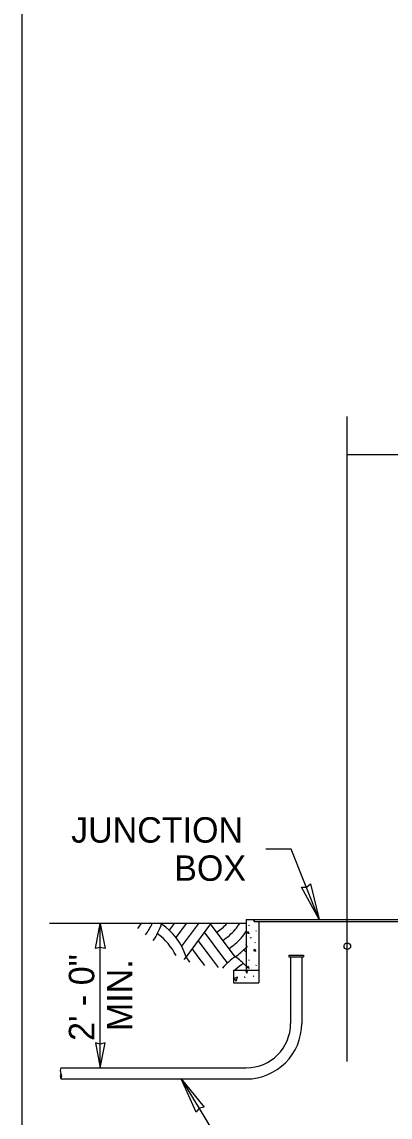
# Model space of a CAD drawing. Extents: x 99862 to 103680, y 99470 to 105076.
# Drawn here: x 99862 to 100094, y 100349 to 101038 of the extents above; entities that cross this region are included whole.
import ezdxf

# ---------------------------------------------------------------- set-up
doc = ezdxf.new("R2010")
doc.units = 0
for name, color, linetype in [('Level 1', 7, 'Continuous'), ('Level 13', 7, 'Continuous'), ('Level 15', 7, 'Continuous'), ('Level 20', 7, 'Continuous'), ('Level 3', 7, 'Continuous')]:
    doc.layers.add(name, color=color, linetype=linetype)

msp = doc.modelspace()

# ---------------------------------------------------------------- linework, layer by layer
at = {"layer": 'Level 1'}
for p, q in [((100003.06, 100472.96), (100003.06, 100441.13)), ((100003.06, 100472.96), (100007.86, 100472.96)), ((100005.03, 100468.93), (100004.85, 100469.35)), ((100007.86, 100472.96), (100007.86, 100471.64)), ((100008.2, 100471.64), (100007.86, 100471.64)), ((100011.02, 100471.64), (100011.02, 100469.62)), ((100011.02, 100469.62), (100011.02, 100441.13)), ((100005.82, 100461.44), (100005.64, 100461.16)), ((100006.14, 100461.55), (100005.95, 100461.27)), ((100009.29, 100465.88), (100009.24, 100465.46)), ((100003.79, 100455.81), (100003.06, 100457.18)), ((100003.06, 100455.86), (100003.74, 100455.81)), ((100008.86, 100458.12), (100008.68, 100458.53)), ((100005.03, 100447.21), (100004.85, 100447.62)), ((99995.1, 100441.13), (99995.1, 100433.17)), ((99995.1, 100441.13), (100011.02, 100441.13)), ((100009.29, 100444.15), (100009.24, 100443.74)), ((100011.02, 100441.13), (100011.02, 100433.17)), ((99995.1, 100433.17), (100011.02, 100433.17)), ((100002.24, 100436.69), (100001.91, 100436.62)), ((100002.54, 100436.54), (100002.21, 100436.47)), ((100007.83, 100437.37), (100007.51, 100437.11))]:
    msp.add_line(p, q, dxfattribs=at)
msp.add_lwpolyline([(99862, 99999.5), (103151, 99999.5), (103151, 102075.5), (99862, 102075.5)], close=True, dxfattribs=at)
for points in [[(100004.94, 100464.08), (100004.39, 100465.24), (100003.46, 100464.54), (100004.94, 100464.08)], [(100009.19, 100452.89), (100008.63, 100454.05), (100007.71, 100453.36), (100009.19, 100452.89)], [(100003.49, 100439.17), (100003.91, 100440.38), (100002.77, 100440.55), (100003.49, 100439.17)], [(100004.94, 100442.35), (100004.39, 100443.51), (100003.46, 100442.82), (100004.94, 100442.35)], [(99996.82, 100434.14), (99997.6, 100436.69), (99995.38, 100435.84), (99996.79, 100434.17)]]:
    msp.add_lwpolyline(points, dxfattribs=at)
msp.add_circle((100066.69, 100456.05), 2.07, dxfattribs=at)
at = {"layer": 'Level 13'}
for p, q in [((100003.06, 100470.31), (99879.38, 100470.31)), ((99949.96, 100470.31), (99949.78, 100470.08)), ((99957.69, 100470.31), (99954.63, 100466.23)), ((99965.42, 100470.31), (99958.87, 100461.58)), ((99973.15, 100470.31), (99962.46, 100456.06)), ((99980.71, 100470.08), (99965.24, 100449.46)), ((99980.71, 100470.08), (99980.53, 100470.31)), ((99996.17, 100449.46), (99980.71, 100470.08)), ((99980.71, 100449.46), (99972.97, 100459.77)), ((99988.44, 100449.46), (99976.84, 100464.92)), ((99972.97, 100449.46), (99969.11, 100454.62)), ((99965.24, 100449.46), (99963.93, 100447.71)), ((99967.73, 100446.14), (99965.24, 100449.46)), ((99977.03, 100444.06), (99972.97, 100449.46)), ((99985.75, 100442.73), (99980.71, 100449.46)), ((99991.32, 100445.62), (99988.44, 100449.46))]:
    msp.add_line(p, q, dxfattribs=at)
for centre, start, end in [((99904.77, 100492.24), 320.31796, 325.90411), ((99908.63, 100487.09), 322.6615, 334.60487), ((99912.5, 100481.94), 325.21602, 342.3566), ((99971.61, 100502.55), 235.48949, 236.09639), ((99927.96, 100437.6), 17.6434, 56.09639), ((99958.88, 100502.55), 303.90361, 304.51051), ((99962.75, 100497.4), 303.90361, 316.18748), ((99966.61, 100492.24), 303.90361, 319.05846), ((99966.61, 100492.24), 319.05839, 325.90411), ((99924.09, 100432.45), 27.05682, 53.69375), ((99970.48, 100487.09), 311.04008, 326.37514), ((99970.48, 100487.09), 303.90361, 311.04014), ((99974.34, 100481.94), 303.90361, 317.21351), ((99978.21, 100422.14), 50.57266, 53.669), ((100017.99, 100416.99), 123.90366, 139.6464), ((99974.34, 100416.99), 42.78649, 56.09639), ((100021.86, 100411.83), 131.04025, 131.52275), ((100021.86, 100411.83), 121.45354, 131.04032)]:
    msp.add_arc(centre, 39.13, start, end, dxfattribs=at)
at = {"layer": 'Level 15'}
for p, q in [((100066.69, 100383.68), (100066.69, 100789.38)), ((100066.69, 100765.36), (100274.6, 100765.36)), ((99911.29, 100379.59), (99911.29, 100470.31))]:
    msp.add_line(p, q, dxfattribs=at)
for points in [[(100048.9, 100472.96), (100031.34, 100517.24), (100015.34, 100517.24)], [(99962.22, 100372.78), (100020.61, 100276.27), (100036.61, 100276.27)]]:
    msp.add_lwpolyline(points, dxfattribs=at)
for points in [[(100048.9, 100472.96), (100037.91, 100493.19), (100041.07, 100493.28), (100043.48, 100495.34)], [(99911.29, 100470.31), (99914.37, 100454.58), (99911.29, 100455.31), (99908.2, 100454.58)], [(99911.29, 100379.59), (99914.37, 100395.31), (99911.29, 100394.58), (99908.2, 100395.31)], [(99962.22, 100372.78), (99976.67, 100354.85), (99973.57, 100354.2), (99971.58, 100351.74)]]:
    msp.add_lwpolyline(points, close=True, dxfattribs=at)
for centre, start, end in [((99889.61, 100377.84), 150, 210), ((99889.61, 100374.34), 150, 210), ((99883.55, 100374.34), 330, 30)]:
    msp.add_arc(centre, 3.5, start, end, dxfattribs=at)
at = {"layer": 'Level 3'}
for p, q in [((100008.2, 100472.96), (100008.2, 100471.64)), ((100008.2, 100472.96), (100125.26, 100472.96)), ((100008.2, 100471.64), (100125.26, 100471.64)), ((100029.86, 100450.4), (100039.18, 100450.4)), ((100029.86, 100450.4), (100029.86, 100449.33)), ((100029.86, 100449.33), (100039.18, 100449.33)), ((100031.02, 100449.33), (100031.02, 100407.55)), ((100038.01, 100449.33), (100038.01, 100407.55)), ((100039.18, 100450.4), (100039.18, 100449.33)), ((99886.58, 100379.59), (100003.06, 100379.59)), ((99886.58, 100372.59), (100003.06, 100372.59))]:
    msp.add_line(p, q, dxfattribs=at)
for radius, end in [(27.96, 0), (34.96, 360)]:
    msp.add_arc((100003.06, 100407.55), radius, 270, end, dxfattribs=at)

# ---------------------------------------------------------------- texts
at = {"layer": 'Level 20'}
for s, p in [('JUNCTION', (99892.95, 100521.24)), ('BOX', (99957.83, 100497.24))]:
    msp.add_text(s, height=16, dxfattribs=at).set_placement(p)
for s, p in [('2\' - 0"', (99907.52, 100396.55)), ('MIN.', (99931.52, 100402.71))]:
    msp.add_text(s, height=16, rotation=90, dxfattribs=at).set_placement(p)

doc.saveas('drawing.dxf')
